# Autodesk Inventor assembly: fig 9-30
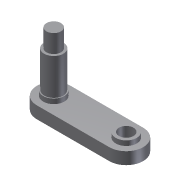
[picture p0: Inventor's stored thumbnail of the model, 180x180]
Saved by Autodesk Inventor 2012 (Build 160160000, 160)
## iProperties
Shininess: 64.0
Length Units: 11269
Angle Units: 11279
Time Units: 11290
Mass Units: 11283
Length Display Precision: 3
Angle Display Precision: 2
Created: 2002-01
Part Number: fig 9-30
Document SubType Name: Assembly
Designer: ***
Density: 0.0
Volumn: 0.0
Area: 0.0
PropertySet Name: Model Information
Control State: 0
Master: False
Checked Out: False
Author: ***
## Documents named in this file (3)
- C:\Users\CadCim\Documents\SAILESH\inventor-2011-fact-prt\c09_inv_2011-prt\c09_inv_2012_prt\fig 9-30.iam
- C:\Users\CadCim\Documents\SAILESH\inventor-2011-fact-prt\c09_inv_2011-prt\c09_inv_2012_prt\Part5.ipt
- C:\Users\CadCim\Documents\SAILESH\inventor-2011-fact-prt\c09_inv_2011-prt\c09_inv_2012_prt\Part6.ipt
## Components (2 placed, 2 different names)
1. Part5:1 — Insert:1
2. Part6:1 — Insert:1
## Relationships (1: Insert 1)
- Insert:1: Part5:1 ↔ Part6:1
